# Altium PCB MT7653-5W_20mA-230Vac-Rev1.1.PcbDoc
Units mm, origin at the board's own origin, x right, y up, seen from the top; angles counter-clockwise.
Board outline 45.76 x 45.99 mm, 2 copper layers (Top Layer, Bottom Layer); 33 components, 55 nets, 78 pads, 0 vias.
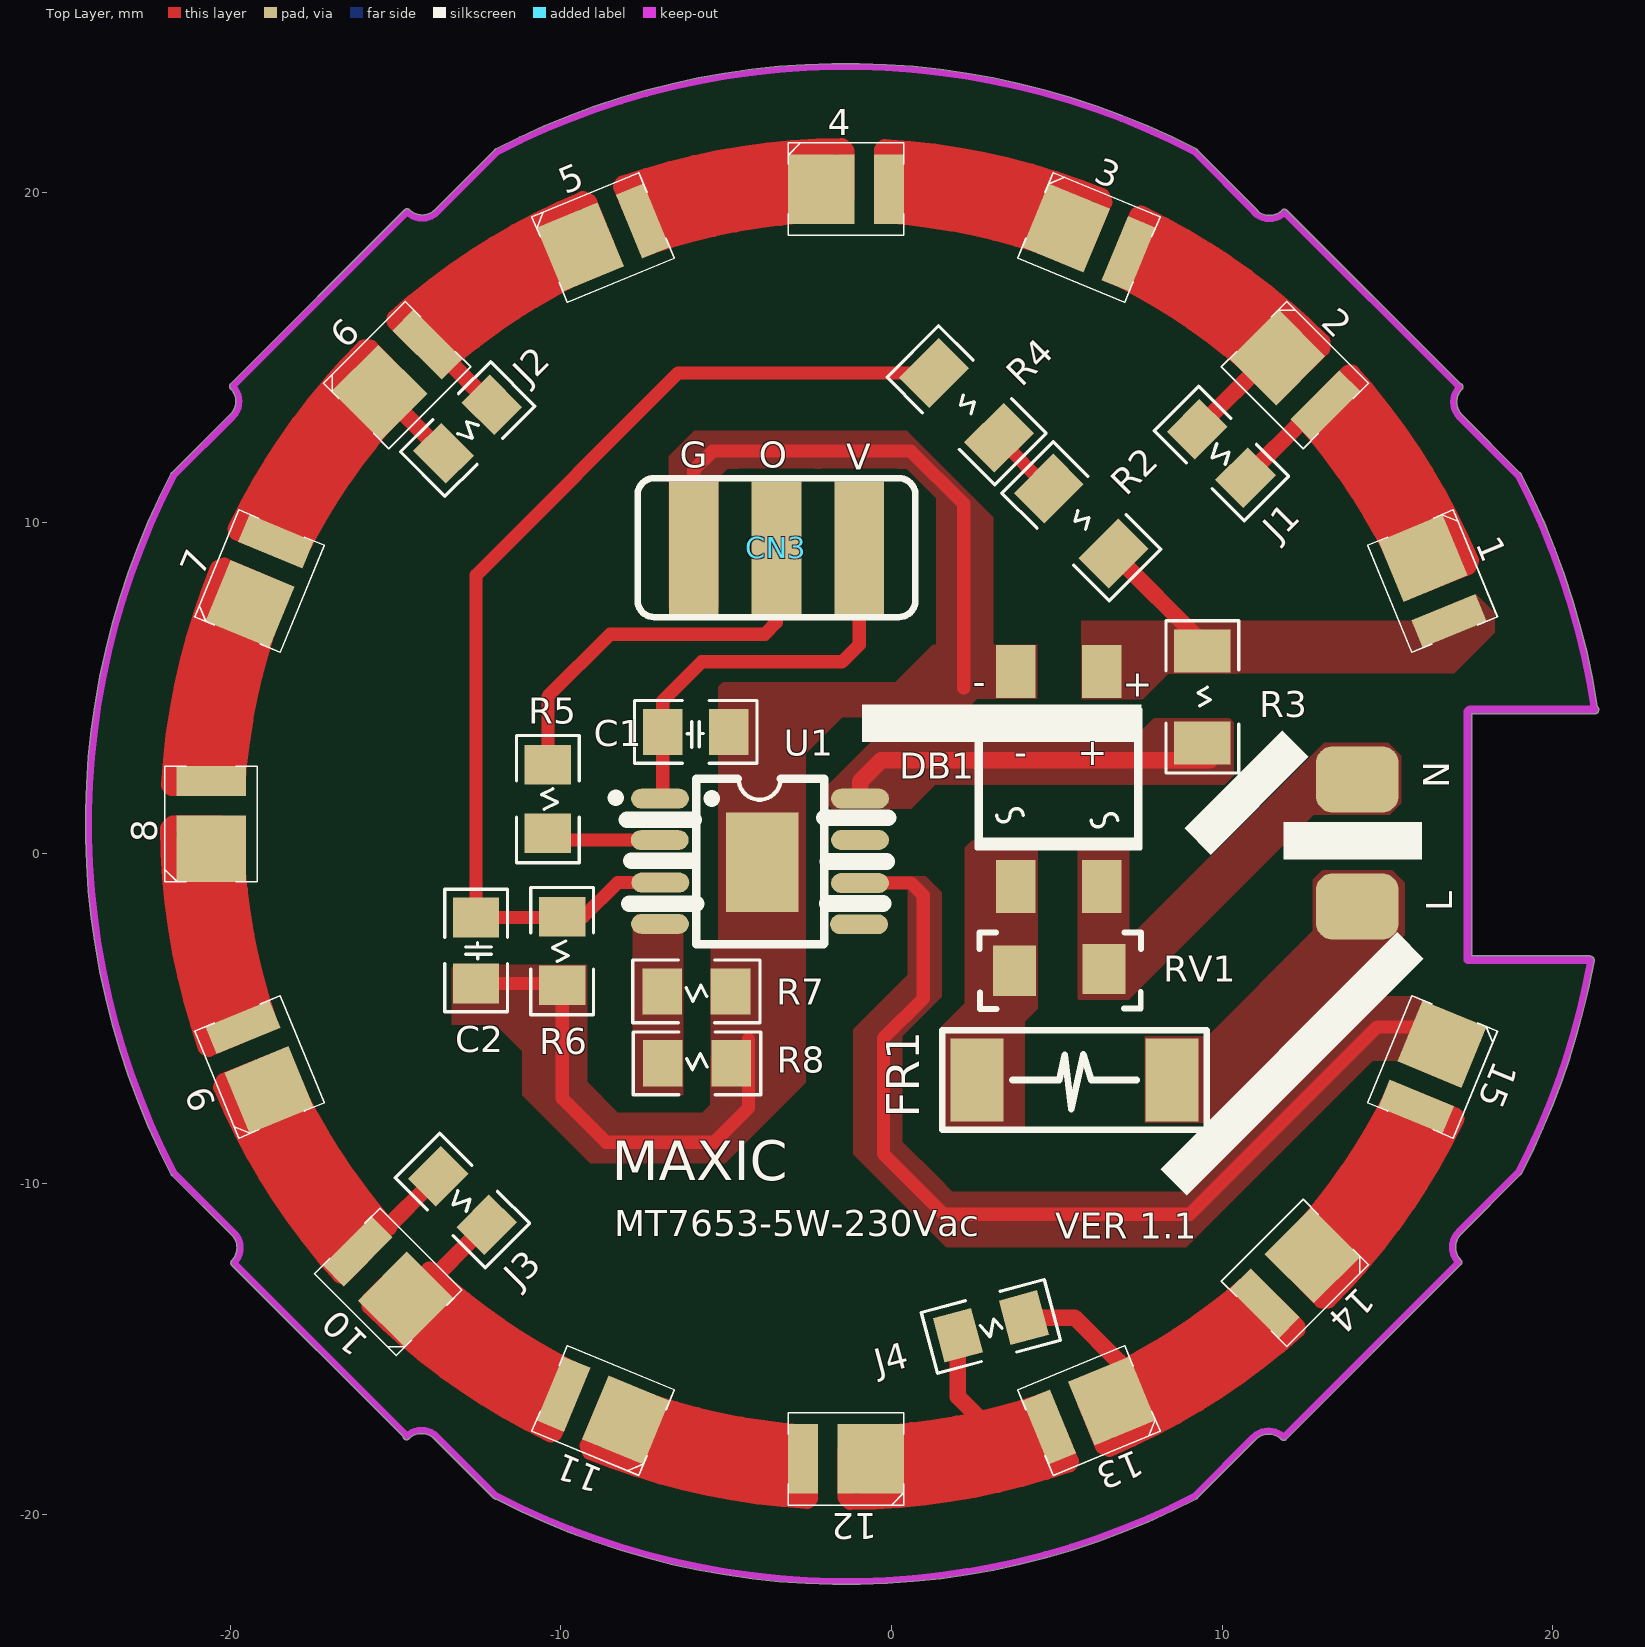
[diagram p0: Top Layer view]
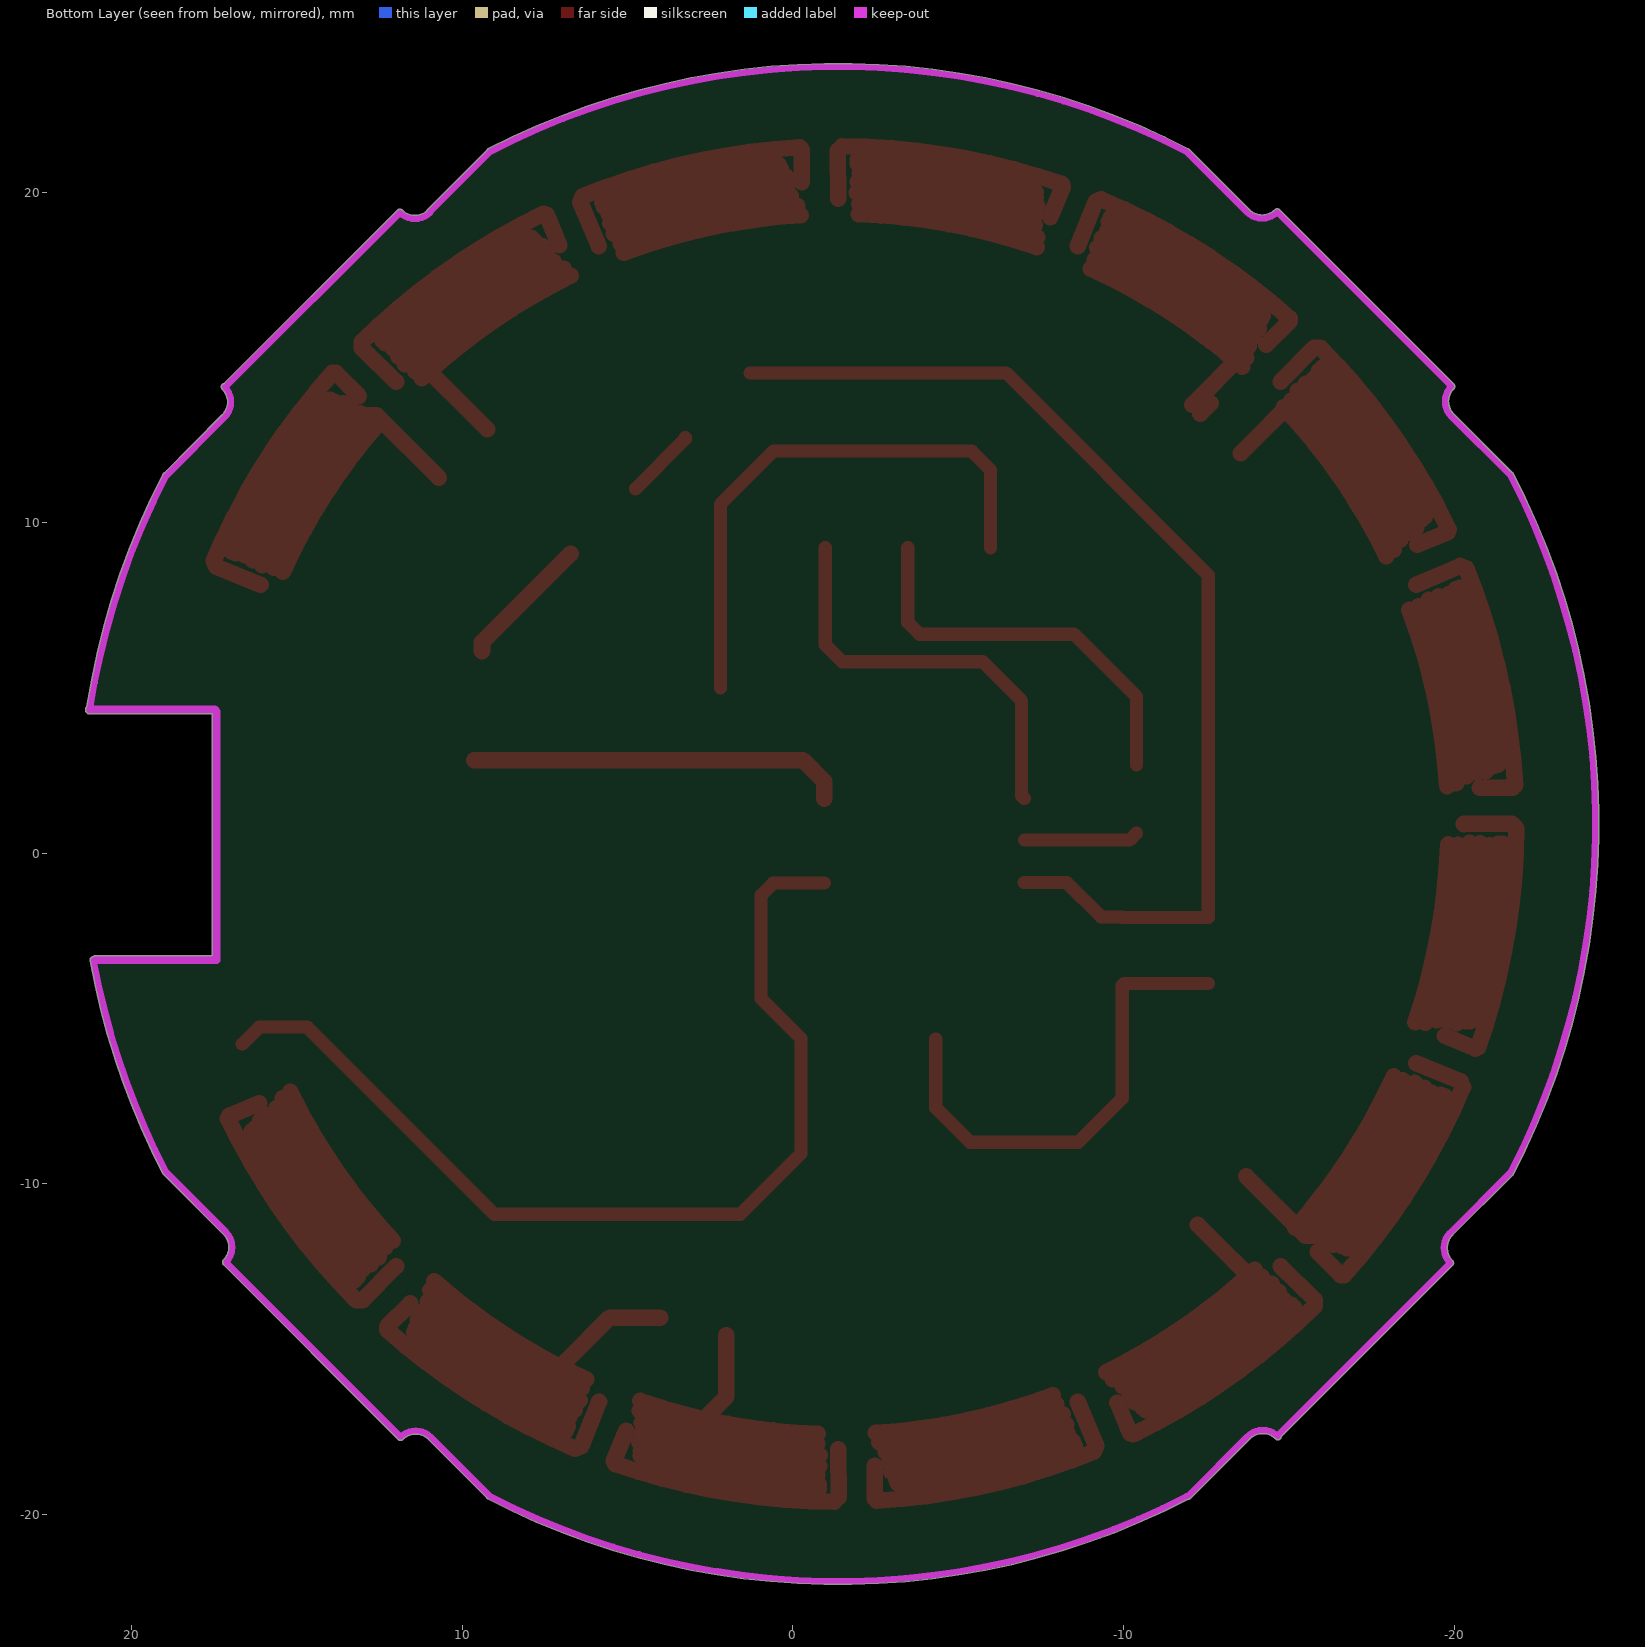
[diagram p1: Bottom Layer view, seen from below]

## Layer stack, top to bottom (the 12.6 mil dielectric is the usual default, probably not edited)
Top Solder: solder mask 0.0102, Solder Resist, Dk 3.5
Top Layer: signal copper 0.0356
Dielectric1: dielectric 0.32, FR-4, Dk 4.8
Bottom Layer: signal copper 0.0356
Bottom Solder: solder mask 0.0102, Solder Resist, Dk 3.5

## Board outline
-19.954,-12.457 cw(c-19.884,-12.385) -19.984,-12.385 cw(c-19.884,-12.385) -19.954,-12.314 ccw(c-20.34,-11.929) -19.795,-11.929 ccw(c-20.34,-11.929) -19.955,-11.543 -21.744,-9.754 cw(c-21.703,-9.662) -21.792,-9.708 cw(c-1.378,0.888) -21.792,11.483 cw(c-21.703,11.437) -21.746,11.528 -19.991,13.283 cw(c-19.92,13.212) -19.99,13.284 ccw(c-20.376,13.669) -19.831,13.669 ccw(c-20.376,13.669) -19.99,14.054 ccw(c-20.376,13.669) -19.991,14.054 -19.99,14.054 cw(c-19.92,14.125) -19.991,14.196 -14.723,19.464 -14.722,19.465 -14.723,19.464 cw(c-14.651,19.394) -14.651,19.494 cw(c-14.651,19.394) -14.58,19.464 cw(c-14.195,19.85) -14.58,19.465 -14.58,19.464 ccw(c-14.195,19.85) -13.809,19.465 -12.018,21.256 cw(c-11.927,21.213) -11.973,21.302 cw(c-1.378,0.888) 9.211,21.305 cw(c9.165,21.216) 9.258,21.255 11.051,19.462 cw(c10.98,19.391) 11.076,19.421 ccw(c11.427,19.838) 11.812,19.452 cw(c11.883,19.381) 11.883,19.482 cw(c11.883,19.381) 11.955,19.452 11.954,19.452 11.955,19.452 17.201,14.206 cw(c17.182,14.107) 17.282,14.107 cw(c17.182,14.107) 17.253,14.036 ccw(c17.638,13.651) 17.251,13.267 cw(c17.181,13.195) 17.252,13.266 19.004,11.505 cw(c18.959,11.416) 19.048,11.462 cw(c-1.378,0.888) 21.347,4.436 cw(c21.26,4.343) 21.387,4.343 cw(c21.26,4.343) 21.26,4.216 17.554,4.216 17.554,-3.098 21.091,-3.098 cw(c21.091,-3.226) 21.177,-3.131 cw(c21.149,-3.228) 21.25,-3.228 cw(c21.149,-3.228) 21.248,-3.246 cw(c-1.378,0.888) 19.051,-9.68 cw(c18.962,-9.634) 19.013,-9.721 cw(c18.936,-9.656) 19.007,-9.727 17.217,-11.526 cw(c17.146,-11.455) 17.217,-11.526 ccw(c17.602,-11.911) 17.216,-12.296 cw(c17.146,-12.368) 17.246,-12.368 cw(c17.146,-12.368) 17.217,-12.439 11.93,-17.725 cw(c11.859,-17.654) 11.788,-17.725 ccw(c11.403,-18.111) 11.018,-17.725 ccw(c11.403,-18.111) 11.017,-17.725 cw(c10.946,-17.654) 11.017,-17.725 ccw(c10.946,-17.654) 11.018,-17.725 11.017,-17.725 9.263,-19.48 cw(c9.172,-19.438) 9.218,-19.527 cw(c-1.378,0.888) -11.952,-19.538 cw(c-11.906,-19.449) -11.963,-19.531 cw(c-11.961,-19.431) -12.032,-19.502 -13.828,-17.706 cw(c-13.757,-17.635) -13.828,-17.706 ccw(c-14.214,-18.091) -14.573,-17.681 cw(c-14.651,-17.618) -14.594,-17.7 ccw(c-14.214,-18.091) -14.599,-17.706 cw(c-14.67,-17.635) -14.77,-17.641

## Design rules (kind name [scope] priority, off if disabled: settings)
Clearance [All] p1: gap=0.4
ComponentClearance [All] p1 off: gap=0.254 collisioncheckmode=3 verticalgap=0.254 showdistances=FALSE
Height [All] p1 off: minheight=0 maxheight=25.4 prefheight=12.7
HoleSize [All] p1 off: absolutevalues=TRUE maxlimit=2.54 minlimit=0.025 maxpercent=80.000 minpercent=20.000
HoleToHoleClearance [All] p1 off: gap=0.254 allowstackedmicrovias=TRUE
LayerPairs [All] p1 off: enforce=TRUE
MinimumSolderMaskSliver [All] p1 off: minsoldermaskwidth=0.254
NetAntennae [All] p1 off: netantennaetolerance=0
PolygonConnect [All] p1: connectstyle=Direct reliefconductorwidth=0.254 reliefentries=4 polygonreliefangle="90 Angle" airgapwidth=0.254
RoutingVias [All] p1: holewidth=0.711 width=1.27 viastyle="Through Hole" minholewidth=0.711 minwidth=1.27 maxholewidth=0.711 maxwidth=1.27
SilkToSilkClearance [All] p1 off: silktosilkclearance=0.254
SilkToSolderMaskClearance SilkscreenOverComponentPads [IsPad] p1 off: minsilkscreentomaskgap=0.254 clearancetoexposedcopper=TRUE
SolderMaskExpansion [All] p1: expansion=0.102
UnRoutedNet [All] p1 off:
UnpouredPolygon [All] p1 off:
Width [All] p1: maxlimit=3 minlimit=0.254 preferedwidth=0.5
19 further rules are at their usual default settings.

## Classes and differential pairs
component class MT7865-20W: Rl T1*1 T1*2

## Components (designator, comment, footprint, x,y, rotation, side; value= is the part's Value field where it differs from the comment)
1 "Comment" "LED 2835亿光/艾笛森/国星/普瑞（阻焊）新" 16.361,8.235 r292.5 top
2 "Comment" "LED 2835亿光/艾笛森/国星/普瑞（阻焊）新" 12.199,14.464 r315 top
3 "Comment" "LED 2835亿光/艾笛森/国星/普瑞（阻焊）新" 5.97,18.626 r337.5 top
4 "Comment" "LED 2835亿光/艾笛森/国星/普瑞（阻焊）新" -1.378,20.087 r0 top
5 "Comment" "LED 2835亿光/艾笛森/国星/普瑞（阻焊）新" -8.725,18.626 r22.5 top
6 "Comment" "LED 2835亿光/艾笛森/国星/普瑞（阻焊）新" -14.954,14.464 r45 top
7 "Comment" "LED 2835亿光/艾笛森/国星/普瑞（阻焊）新" -19.116,8.235 r67.5 top
8 "Comment" "LED 2835亿光/艾笛森/国星/普瑞（阻焊）新" -20.578,0.887 r90 top
9 "Comment" "LED 2835亿光/艾笛森/国星/普瑞（阻焊）新" -19.116,-6.46 r112.5 top
10 "Comment" "LED 2835亿光/艾笛森/国星/普瑞（阻焊）新" -15.223,-12.958 r135 top
11 "Comment" "LED 2835亿光/艾笛森/国星/普瑞（阻焊）新" -8.725,-16.851 r157.5 top
12 "Comment" "LED 2835亿光/艾笛森/国星/普瑞（阻焊）新" -1.378,-18.313 r180 top
13 "Comment" "LED 2835亿光/艾笛森/国星/普瑞（阻焊）新" 5.97,-16.851 r202.5 top
14 "Comment" "LED 2835亿光/艾笛森/国星/普瑞（阻焊）新" 12.199,-12.689 r225 top
15 "Comment" "LED 2835亿光/艾笛森/国星/普瑞（阻焊）新" 16.361,-6.46 r247.5 top
C1 "Comment" C/S-0805(T) -5.922,3.671 r180 top
C2 "Comment" C/S-0805(T) -12.567,-2.938 r270 top
CN3 "Comment" "SW/D 3PIN H600公端子 P2.5 贴片" -3.48,9.246 r180 top locked
DB1 "Comment" "BD-MB10G/MMB1010 (B)" 5.052,2.252 r90 top
FR1 "Comment" RXM-0207 5.537,-6.854 r0 top locked
J1 "Comment" R/S-0805(T) 9.974,12.095 r135 top
J2 "Comment" R/S-0805(T) -12.818,12.831 r225 top
J3 "Comment" R/S-0805(T) -12.98,-10.5 r135 top
J4 "Comment" R/S-0805(T) 3.005,-14.307 r195 top
R2 "Comment" R/S-1206(T) 5.735,10.047 r135 top
R3 "Comment" R/S-1206(T) 9.399,4.731 r90 top locked
R4 "Comment" R/S-1206(T) 2.268,13.55 r135 top
R5 "Comment" R/S-0805(T) -10.394,1.642 r270 top
R6 "Comment" R/S-0805(T) -9.963,-2.956 r90 top
R7 "Comment" R/S-0805(T) -5.904,-4.177 r180 top
R8 "Comment" R/S-0805(T) -5.886,-6.351 r0 top
RV1 "Comment" C/S-1206(T)阻焊 5.106,-3.549 r0 top
U1 "Comment" "U IC   SO-8EP/SOIC-8-EP   (B)" -3.982,-0.244 r0 top locked

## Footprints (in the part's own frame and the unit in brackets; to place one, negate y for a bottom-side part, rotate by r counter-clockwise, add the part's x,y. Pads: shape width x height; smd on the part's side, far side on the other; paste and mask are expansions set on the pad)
"BD-MB10G/MMB1010 (B)" [mm]
  rect 1.6x1.2 smd: 1(-3.25,-1.3) 2(3.25,-1.3) 3(-3.25,1.3) 4(3.25,1.3)
  silkscreen extent -2.1,-2.47 2.1,2.47
C/S-0805(T) [mm]
  rect 1.2x1.4 smd: 1(-1,0) 2(1,0)
  silkscreen extent -1.85,-0.95 1.85,0.95
C/S-1206(T)阻焊 [mil]
  rect 51.18x60 smd: 1(-54.63,0) 2(52,2)
  silkscreen extent -96,-46 96,46
"LED 2835亿光/艾笛森/国星/普瑞（阻焊）新" [mm]
  rect 0.9x2.1 smd: A(1.3,0.001)
  rect 2x2.1 smd: K(-0.75,0.001)
  silkscreen extent -1.75,-1.4 1.75,1.4
R/S-0805(T) [mm]
  rect 1.2x1.4 smd: 1(-1.035,0) 2(1.035,0)
  silkscreen extent -1.93,-0.95 1.93,0.95
R/S-1206(T) [mm]
  rect 1.3x1.7 smd: 1(-1.387,0) 2(1.387,0)
  silkscreen extent -2.3,-1.1 2.3,1.1
RXM-0207 [mm]
  rect 1.6x2.5 smd: 1(-2.95,0) 2(2.95,0)
  silkscreen extent -4,-1.5 4,1.5
"SW/D 3PIN H600公端子 P2.5 贴片" [mm]
  rect 1.5x4 smd: 1(-2.5,0) 2(0,0) 3(2.5,0)
  silkscreen extent -4.2,-2.1 4.2,2.1
"U IC   SO-8EP/SOIC-8-EP   (B)" [mm]
  rect 2.2x3.002 smd: 0(0.073,-0.028)
  oval 1.75x0.6 smd: 1(-3.02,1.9) 2(-3.03,0.645) 3(-3.01,-0.64) 4(-3.02,-1.89) 5(3,-1.9) 6(3.025,-0.655) 7(3.03,0.65) 8(3.03,1.9)
  silkscreen extent -4.36,-2.5 3.87,2.51

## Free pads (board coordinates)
  rrect50% 2.5x2 smd: 2(14.086,-1.609) 2(14.086,2.234)

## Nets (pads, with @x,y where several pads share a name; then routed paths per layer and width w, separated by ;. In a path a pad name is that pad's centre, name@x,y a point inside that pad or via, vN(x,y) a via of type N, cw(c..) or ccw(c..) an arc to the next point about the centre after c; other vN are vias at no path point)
1: 1.K 2.A | length 47.9
  Top Layer w0.5: 2.A@12.448,13.105 cw(c-1.378,0.887) 1.K@15.421,8.517 ; 2.A@12.717,13.231 cw(c-1.108,1.013) 1.K@15.691,8.643 ; 2.A@13.076,13.303 cw(c-0.749,1.085) 1.K@16.05,8.714 ; 2.A@13.121,13.831 13.824,14.534 13.921,14.534 cw(c-1.378,0.887) 17.515,8.846 17.439,8.667 1.K@16.098,8.126 ; 2.A@13.364,13.446 cw(c-0.462,1.229) 1.K@16.337,8.858 ; 2.A@13.597,13.608 cw(c-0.228,1.39) 1.K@16.571,9.02 ; 2.A@13.866,13.662 cw(c0.041,1.444) 1.K@16.84,9.074 ; 13.992,13.716 cw(c0.167,1.498) 1.K@16.966,9.127
2: 2.K 3.A | length 47.9
  Top Layer w0.5: 3.A@6.72,17.466 cw(c-1.378,0.887) 2.K@11.223,14.365 ; 3.A@6.921,17.685 cw(c-1.177,1.107) 2.K@11.424,14.584 ; 3.A@7.065,18.394 7.445,19.312 7.534,19.349 cw(c-1.378,0.887) 13.031,15.47 13.029,15.276 2.K@11.998,14.262 ; 3.A@7.225,17.889 cw(c-0.872,1.311) 2.K@11.728,14.788 ; 3.A@7.435,18.131 cw(c-0.662,1.553) 2.K@11.938,15.03 ; 3.A@7.589,18.37 cw(c-0.508,1.792) 2.K@12.092,15.269 ; 3.A@7.818,18.523 cw(c-0.28,1.945) 2.K@12.321,15.422 ; 7.913,18.621 cw(c-0.184,2.043) 2.K@12.416,15.52
3: 3.K 4.A | length 47.9
  Top Layer w0.5: 4.A@-0.278,20.292 -0.278,21.286 -0.209,21.354 cw(c-1.378,0.887) 6.354,19.874 6.426,19.694 3.K@5.861,18.363 ; 4.A@-0.241,19.302 cw(c-1.378,0.887) 3.K@5.106,18.161 ; 4.A@-0.139,19.582 cw(c-1.276,1.167) 3.K@5.208,18.44 ; 4.A@0.064,19.887 cw(c-1.073,1.472) 3.K@5.411,18.745 ; 4.A@0.166,20.191 cw(c-0.971,1.776) 3.K@5.512,19.05 ; 4.A@0.216,20.471 cw(c-0.92,2.056) 3.K@5.563,19.329 ; 4.A@0.369,20.699 cw(c-0.768,2.284) 3.K@5.716,19.558 ; 0.42,20.826 cw(c-0.717,2.411) 3.K@5.766,19.685
4: 4.K 5.A | length 47.9
  Top Layer w0.5: 5.A@-7.787,19.236 -8.167,20.154 -8.131,20.243 cw(c-1.378,0.887) -1.5,21.387 -1.364,21.249 4.K@-1.377,19.803 ; 5.A@-7.399,19.59 cw(c-1.402,2.142) 4.K@-2.022,20.581 ; 5.A@-7.387,18.633 cw(c-1.391,1.184) 4.K@-2.011,19.624 ; 5.A@-7.374,18.336 cw(c-1.378,0.887) 4.K@-1.998,19.327 ; -7.348,19.996 cw(c-1.351,2.548) 4.K@-1.971,20.988 ; 5.A@-7.346,19.86 cw(c-1.349,2.411) 4.K@-1.969,20.851 ; 5.A@-7.339,19.312 cw(c-1.342,1.864) 4.K@-1.962,20.304 ; 5.A@-7.316,18.992 cw(c-1.32,1.544) 4.K@-1.94,19.983
5: 5.K 6.A | length 47.9
  Top Layer w0.5: 6.A@-14.321,15.386 -15.024,16.089 -15.024,16.186 cw(c-1.378,0.887) -9.336,19.78 -9.157,19.704 5.K@-8.616,18.363 ; -14.206,16.257 cw(c-1.988,2.432) 5.K@-9.618,19.231 ; 6.A@-14.152,16.131 cw(c-1.934,2.306) 5.K@-9.564,19.105 ; 6.A@-14.098,15.862 cw(c-1.88,2.037) 5.K@-9.51,18.836 ; 6.A@-13.936,15.629 cw(c-1.719,1.803) 5.K@-9.348,18.602 ; 6.A@-13.793,15.341 cw(c-1.575,1.516) 5.K@-9.205,18.315 ; 6.A@-13.721,14.982 cw(c-1.503,1.157) 5.K@-9.133,17.955 ; 6.A@-13.595,14.713 cw(c-1.378,0.887) 5.K@-9.007,17.686
6: 6.K 7.A | length 47.9
  Top Layer w0.5: -19.111,10.178 cw(c-2.533,2.081) 6.K@-16.01,14.681 ; 7.A@-19.013,10.083 cw(c-2.435,1.985) 6.K@-15.912,14.586 ; 7.A@-18.884,9.33 -19.802,9.71 -19.839,9.799 cw(c-1.378,0.887) -15.96,15.296 -15.766,15.294 6.K@-14.752,14.263 ; 7.A@-18.86,9.854 cw(c-2.282,1.757) 6.K@-15.759,14.357 ; 7.A@-18.622,9.7 cw(c-2.043,1.603) 6.K@-15.521,14.203 ; 7.A@-18.379,9.49 cw(c-1.801,1.393) 6.K@-15.278,13.993 ; 7.A@-18.175,9.186 cw(c-1.597,1.088) 6.K@-15.074,13.688 ; 7.A@-17.956,8.985 cw(c-1.378,0.887) 6.K@-14.855,13.488
7: 7.K 8.A | length 47.9
  Top Layer w0.5: -21.316,2.685 cw(c-2.902,1.548) 7.K@-20.175,8.031 ; 8.A@-21.189,2.634 cw(c-2.775,1.497) 7.K@-20.048,7.981 ; 8.A@-20.961,2.481 cw(c-2.546,1.345) 7.K@-19.819,7.828 ; 8.A@-20.782,1.987 -21.776,1.987 -21.844,2.055 cw(c-1.378,0.887) -20.364,8.619 -20.184,8.691 7.K@-18.853,8.126 ; 8.A@-20.681,2.431 cw(c-2.267,1.294) 7.K@-19.54,7.777 ; 8.A@-20.377,2.329 cw(c-1.962,1.192) 7.K@-19.235,7.676 ; 8.A@-20.072,2.126 cw(c-1.657,0.989) 7.K@-18.93,7.473 ; 8.A@-19.792,2.024 cw(c-1.378,0.887) 7.K@-18.651,7.371
8: 8.K 9.A | length 47.9
  Top Layer w0.5: 8.K@-21.478,0.294 ccw(c-3.038,0.914) -20.486,-5.083 ; 8.K@-21.341,0.296 ccw(c-2.901,0.916) 9.A@-20.35,-5.081 ; 8.K@-21.072,0.243 ccw(c-2.632,0.863) 9.A@-20.08,-5.134 ; 8.K@-20.794,0.303 ccw(c-2.354,0.923) 9.A@-19.803,-5.074 ; 8.K@-20.473,0.325 ccw(c-2.034,0.945) 9.A@-19.482,-5.051 ; 8.K@-20.293,0.888 -21.739,0.901 -21.877,0.765 ccw(c-1.378,0.887) -20.733,-5.866 -20.644,-5.903 9.A@-19.726,-5.522 ; 8.K@-20.114,0.254 ccw(c-1.675,0.874) 9.A@-19.123,-5.123 ; 8.K@-19.817,0.267 ccw(c-1.378,0.887) 9.A@-18.826,-5.109
9: 9.K 10.A | length 47.9
  Top Layer w0.5: 9.K@-19.721,-7.353 ccw(c-2.922,0.277) -16.747,-11.941 ; 9.K@-19.595,-7.299 ccw(c-2.796,0.331) 10.A@-16.622,-11.887 ; 9.K@-19.326,-7.245 ccw(c-2.527,0.385) 10.A@-16.352,-11.833 ; 9.K@-19.092,-7.083 ccw(c-2.294,0.546) 10.A@-16.119,-11.671 ; 9.K@-18.853,-6.351 -20.194,-6.892 -20.27,-7.071 ccw(c-1.378,0.887) -16.676,-12.759 -16.579,-12.759 10.A@-15.876,-12.056 ; 9.K@-18.805,-6.94 ccw(c-2.006,0.69) 10.A@-15.831,-11.528 ; 9.K@-18.446,-6.868 ccw(c-1.647,0.762) 10.A@-15.472,-11.456 ; 9.K@-18.176,-6.742 ccw(c-1.378,0.887) -15.203,-11.33
10: 10.K 11.A | length 47.9
  Top Layer w0.5: 10.K@-15.171,-13.745 ccw(c-2.571,-0.268) -10.668,-16.846 ; 10.K@-15.076,-13.647 ccw(c-2.475,-0.17) 11.A@-10.573,-16.748 ; 10.K@-14.847,-13.494 ccw(c-2.247,-0.017) 11.A@-10.344,-16.595 ; 10.K@-14.753,-12.487 -15.784,-13.501 -15.786,-13.695 ccw(c-1.378,0.887) -10.289,-17.574 -10.2,-17.537 11.A@-9.82,-16.619 ; 10.K@-14.694,-13.256 ccw(c-2.093,0.222) 11.A@-10.191,-16.357 ; 10.K@-14.483,-13.013 ccw(c-1.883,0.464) 11.A@-9.98,-16.114 ; 10.K@-14.179,-12.809 ccw(c-1.578,0.668) 11.A@-9.676,-15.91 ; -13.978,-12.59 ccw(c-1.378,0.887) 11.A@-9.475,-15.691
11: 11.K 12.A | length 47.9
  Top Layer w0.5: 11.K@-8.617,-16.588 -9.182,-17.919 -9.109,-18.099 ccw(c-1.378,0.887) -2.546,-19.579 -2.478,-19.511 12.A@-2.478,-18.517 ; 11.K@-8.522,-17.91 ccw(c-2.038,-0.637) -3.175,-19.052 ; 11.K@-8.471,-17.783 ccw(c-1.987,-0.51) 12.A@-3.124,-18.925 ; 11.K@-8.318,-17.554 ccw(c-1.835,-0.281) 12.A@-2.971,-18.696 ; 11.K@-8.268,-17.275 ccw(c-1.784,-0.002) 12.A@-2.921,-18.417 ; 11.K@-8.166,-16.97 ccw(c-1.682,0.303) 12.A@-2.819,-18.112 ; 11.K@-7.963,-16.665 ccw(c-1.479,0.608) 12.A@-2.616,-17.807 ; 11.K@-7.861,-16.386 ccw(c-1.378,0.887) 12.A@-2.514,-17.528
12: 12.K 13.A | length 47.9
  Top Layer w0.5: 12.K@-1.378,-18.028 -1.391,-19.474 -1.255,-19.612 ccw(c-1.378,0.887) 5.376,-18.468 5.412,-18.379 13.A@5.032,-17.461 ; 12.K@-0.815,-18.209 ccw(c-1.436,0.231) 13.A@4.561,-17.217 ; 12.K@-0.793,-18.529 ccw(c-1.413,-0.089) 13.A@4.584,-17.538 ; 12.K@-0.786,-19.076 ccw(c-1.406,-0.637) 13.A@4.591,-18.085 ; 12.K@-0.784,-19.213 ccw(c-1.404,-0.773) 4.592,-18.222 ; 12.K@-0.757,-17.552 ccw(c-1.378,0.887) 13.A@4.619,-16.561 ; 12.K@-0.744,-17.849 ccw(c-1.364,0.59) 13.A@4.632,-16.858 ; 12.K@-0.733,-18.807 ccw(c-1.353,-0.367) 13.A@4.644,-17.815
13: 13.K 14.A | length 47.9
  Top Layer w0.5: 13.K@5.861,-16.588 6.402,-17.929 6.581,-18.005 ccw(c-1.378,0.887) 12.269,-14.411 12.269,-14.314 14.A@11.566,-13.612 ; 13.K@6.252,-15.911 ccw(c-1.378,0.887) 14.A@10.84,-12.938 ; 13.K@6.378,-16.181 ccw(c-1.252,0.618) 14.A@10.966,-13.207 ; 13.K@6.449,-16.54 ccw(c-1.18,0.259) 14.A@11.038,-13.566 ; 13.K@6.593,-16.827 ccw(c-1.036,-0.029) 14.A@11.181,-13.854 ; 13.K@6.755,-17.061 ccw(c-0.875,-0.262) 14.A@11.343,-14.087 ; 13.K@6.809,-17.33 ccw(c-0.821,-0.531) 14.A@11.397,-14.357 ; 13.K@6.863,-17.456 ccw(c-0.767,-0.657) 11.451,-14.482
14: 14.K 15.A | length 47.9
  Top Layer w0.5: 14.K@11.997,-12.488 13.011,-13.519 13.205,-13.521 ccw(c-1.378,0.887) 17.084,-8.024 17.047,-7.935 15.A@16.129,-7.555 ; 14.K@12.1,-11.713 ccw(c-1.378,0.887) 15.A@15.201,-7.21 ; 14.K@12.319,-11.914 ccw(c-1.158,0.687) 15.A@15.42,-7.411 ; 14.K@12.523,-12.218 ccw(c-0.954,0.382) 15.A@15.624,-7.715 ; 14.K@12.765,-12.429 ccw(c-0.712,0.172) 15.A@15.866,-7.926 ; 14.K@13.004,-12.582 ccw(c-0.473,0.018) 15.A@16.105,-8.079 ; 14.K@13.157,-12.811 ccw(c-0.32,-0.21) 15.A@16.258,-8.308 ; 14.K@13.255,-12.906 ccw(c-0.222,-0.306) 16.356,-8.403
15: 
A: 
A1: 
A2: 
A3: 
A4: 
A5: 
A6: 
A7: 
A8: 
A9: 
A10: 
A11: 
A12: 
A13: 
A14: 
A15: 
C-: 
CS: R7.2 R8.1 U1.4
CS1: 
CS2: 
DC-: 
DW-: 
GND: C1.1 C2.2 CN3.3 DB1.4 R6.1 R7.1 R8.2 U1.0 | length 31.7
  Top Layer w0.4: C2.2 -10.016,-3.938 R6.1 -9.963,-7.41 -8.634,-8.739 -5.365,-8.739 -4.323,-7.698 -4.323,-5.614 ; CN3.3 -5.98,11.597 -5.41,12.167 0.584,12.167 2.184,10.566 2.184,5.004
L: DB1.3 FR1.1 RV1.1
L+: FR1.2 pad.2@14.086,-1.609
N: DB1.1 pad.2@14.086,2.234 RV1.2
OUT: 15.K U1.6 | length 30.6
  Top Layer w0.4: U1.6 0.589,-0.899 0.957,-1.268 0.957,-4.393 -0.246,-5.596 -0.246,-9.081 1.586,-10.913 9.022,-10.913 14.679,-5.255 16.136,-5.255 15.K
OUT1: 
OUT2: 
PWM: R5.2 U1.2 | length 3.5
  Top Layer w0.4: R5.2 -10.188,0.401 U1.2
PWM+: CN3.2 R5.1 | length 13.5
  Top Layer w0.4: -10.394,3.957 R5.1 -10.394,4.745 -8.509,6.629 -3.835,6.629 -3.48,6.985 CN3.2
R2+: R2.2 R4.1 | length 2.2
  Top Layer w0.4: R4.1 3.25,12.533 R2.2
RD: C2.1 R4.2 R6.2 U1.3 | length 32.8
  Top Layer w0.4: U1.3 -8.286,-0.884 -9.323,-1.921 R6.2 -9.98,-1.938 C2.1 -12.567,8.413 -6.449,14.531 R4.2
SEL: 
VBUS: 
VCC: C1.2 CN3.1 U1.1 | length 12.6
  Top Layer w0.4: U1.1 -6.922,1.736 C1.2 -6.922,4.61 -5.74,5.791 -1.499,5.791 -0.98,6.31 CN3.1
VDC+: 
VIN: R3.1 U1.8 | length 11.4
  Top Layer w0.5: U1.8 -0.952,2.175 -0.304,2.823 R3.1@9.632,2.823
VLED+: 1.A DB1.2 R2.1 R3.2 | length 4.1
  Top Layer w0.5: R2.1 9.399,6.383 R3.2
W-: 
pads on no net: J1.1 J1.2 J2.1 J2.2 J3.1 J3.2 J4.1 J4.2 U1.5 U1.7
copper on no net: | length 27.5
  Top Layer w0.5: -16.087,-11.559 -15.503,-11.559 -13.712,-9.768 ; -15.818,13.855 -15.809,13.855 ; -15.278,13.993 -15.278,13.827 -13.55,12.099 ; -14.309,-13.373 -14.309,-13.292 -12.248,-11.231 ; -13.591,15.759 -13.591,15.067 -12.087,13.563 ; -13.088,15.938 -12.639,15.489 ; -12.639,13.612 -12.32,13.294 ; 2.005,-14.575 2.005,-16.433 3.292,-17.72 ; 4.005,-14.039 5.539,-14.039 6.866,-15.367 6.866,-16.48 ; 9.242,12.827 11.445,15.03 11.938,15.03 ; 10.705,11.363 12.587,13.244 12.955,13.244

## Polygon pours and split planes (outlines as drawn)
GND on Top Layer "Keep-Out Layer-No Net" (solid, remove dead copper, pour order 326): 3.073,5.41 3.073,10.16 2.21,11.024 0.457,12.776 -1.778,12.776 -5.969,12.776 -6.528,12.217 -6.731,12.014 -6.731,7.442 -5.232,7.442 -5.232,11.354 -4.978,11.608 -4.953,11.633 0,11.633 0.457,11.633 0.686,11.405 1.346,10.744 1.346,5.512
OUT on Top Layer "Keep-Out Layer-No Net" (solid, remove dead copper, pour order 298): -0.336,-0.693 1.029,-0.693 1.119,-0.783 1.514,-1.178 1.514,-1.394 1.514,-4.339 0.993,-4.86 0.329,-5.524 0.329,-6.387 0.329,-8.721 1.424,-9.817 1.837,-10.23 4.208,-10.23 8.914,-10.23 9.201,-9.943 14.823,-4.321 15.577,-4.321 15.9,-4.321 16.655,-5.075 15.451,-6.279 15.308,-6.279 14.553,-6.279 13.153,-7.68 8.914,-11.918 7.657,-11.918 1.658,-11.918 -0.372,-9.889 -1.162,-9.099 -1.162,-8.165 -1.162,-5.327 -0.084,-4.249 0.49,-3.675 0.49,-2.274 0.49,-1.016 0.373,-0.899 -0.957,-0.899
VLED+ on Top Layer "Keep-Out Layer-No Net" (solid, remove dead copper, pour order 300): 10.476,5.449 17.014,5.449 18.235,6.671 18.235,7.281 17.679,7.838 16.87,7.03 15.721,7.03 8.106,7.03 7.782,6.707 7.172,6.096 7.172,5.413
GND on Top Layer "Keep-Out Layer-No Net" (solid, remove dead copper, pour order 302): -3.82,-8.165 -2.599,-6.943 -2.599,-5.614 -4.467,-5.614 -4.539,-5.542 -4.898,-5.542 -5.455,-6.099 -5.49,-6.135 -5.49,-8.003
GND on Top Layer "Keep-Out Layer-No Net" (solid, remove dead copper, pour order 304): -13.106,-3.369 -9.226,-3.369 -9.208,-3.351 -9.208,-6.907 -8.364,-7.752 -8.274,-7.841 -5.724,-7.841 -5.041,-7.159 -5.041,-6.62 -4.323,-6.62 -3.82,-7.123 -3.82,-8.165 -4.09,-8.434 -5.024,-9.368 -8.005,-9.368 -9.119,-9.368 -10.106,-8.38 -11.166,-7.321 -11.166,-5.991 -11.974,-5.183 -13.303,-5.183 -13.303,-3.351 -13.285,-3.333
GND on Top Layer "Keep-Out Layer-No Net" (solid, remove dead copper, pour order 306): -5.473,-7.123 -5.473,-2.884 -3.928,-1.34 -2.599,-2.669 -2.599,-5.902 -3.82,-7.123
CS on Top Layer "Keep-Out Layer-No Net" (solid, remove dead copper, pour order 308): -7.825,-1.968 -7.825,-7.321 -6.317,-7.321 -6.299,-7.303 -6.299,-1.879 -6.317,-1.861 -7.718,-1.861
GND on Top Layer "Keep-Out Layer-No Net" (solid, remove dead copper, pour order 312): 4.334,6.311 1.245,6.311 0.58,5.647 0.113,5.18 -1.934,5.18 -5.095,5.18 -5.113,5.162 -5.239,5.036 -5.239,-2.794 -2.725,-2.794 -2.599,-2.669 -2.599,3.007 -1.485,4.12 0.131,4.12 2.035,4.12 2.592,4.677 4.388,4.677 4.406,4.695 4.406,6.311
VIN on Top Layer "Keep-Out Layer-No Net" (solid, remove dead copper, pour order 314): -1.413,1.354 0.598,1.354 1.317,2.073 10.081,2.073 10.351,2.342 10.351,4.066 10.369,4.084 7.926,4.084 7.585,3.743 7.261,3.42 4.531,3.42 -0.569,3.42 -1.593,2.396 -1.97,2.019 -1.97,1.66 -1.97,1.516 -1.809,1.354
VLED+ on Top Layer "Keep-Out Layer-No Net" (solid, remove dead copper, pour order 316): 5.735,4.659 7.603,4.659 8.106,5.162 8.375,5.431 10.279,5.431 10.458,5.431 10.476,5.413 10.476,7.03 5.735,7.03
N on Top Layer "Keep-Out Layer-No Net" (solid, remove dead copper, pour order 318): 5.663,-4.429 7.172,-4.429 8.95,-2.651 12.775,1.175 14.535,1.175 15.074,1.175 15.326,1.426 15.416,1.516 15.416,2.773 15.416,2.953 15.128,3.24 15.02,3.348 14.446,3.348 13.081,3.348 12.883,3.15 6.274,-3.459 5.663,-3.459
L+ on Top Layer "Keep-Out Layer-No Net" (solid, remove dead copper, pour order 320): 7.657,-8.147 9.848,-8.147 15.416,-2.579 15.523,-2.471 15.523,-0.998 15.523,-0.891 15.146,-0.514 13.027,-0.514 12.739,-0.801 12.739,-2.345 11.805,-3.279 9.56,-5.524 9.093,-5.524 7.657,-5.524
N on Top Layer "Keep-Out Layer-No Net" (solid, remove dead copper, pour order 322): 5.627,0.277 5.627,-4.393 5.663,-4.429 7.172,-4.429 7.19,-4.447 7.19,0.259 7.172,0.277
L on Top Layer "Keep-Out Layer-No Net" (solid, remove dead copper, pour order 324): 3.939,0.385 2.43,0.385 2.412,0.367 2.215,0.169 2.215,-3.136 2.215,-4.537 1.801,-4.95 1.46,-5.291 1.46,-8.237 1.46,-8.38 1.478,-8.398 4.029,-8.398 4.029,-5.093 4.424,-4.698 4.424,0.367 4.406,0.385

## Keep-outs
Keep-Out Layer:
  lines w0.2: -21.703,-9.662 cw(c-1.378,0.888) -21.703,11.437 ; -21.699,11.433 -19.92,13.212 ccw(c-20.376,13.669) -19.92,14.125 -14.651,19.394 ccw(c-14.195,19.85) -13.738,19.394 -11.923,21.209 ; -21.696,-9.66 -19.884,-11.472 cw(c-20.34,-11.929) -19.884,-12.385 -14.651,-17.618 ; -14.67,-17.635 cw(c-14.214,-18.091) -13.757,-17.635 -11.961,-19.431 ; -11.927,21.213 cw(c-1.378,0.888) 9.165,21.216 ; -11.906,-19.449 ccw(c-1.378,0.888) 9.172,-19.438 ; 9.168,21.203 10.98,19.391 ; 9.188,-19.413 10.946,-17.654 cw(c11.403,-18.111) 11.859,-17.654 17.146,-12.368 cw(c17.602,-11.911) 17.146,-11.455 18.936,-9.656 ; 10.97,19.381 ccw(c11.427,19.838) 11.883,19.381 17.17,14.095 ; 17.181,13.195 18.936,11.431 ; 17.182,13.194 cw(c17.638,13.651) 17.182,14.107 ; 18.959,11.416 cw(c-1.378,0.888) 21.26,4.343 ; 18.962,-9.634 ccw(c-1.378,0.888) 21.149,-3.228
  lines w0.254: 21.091,-3.226 17.427,-3.226 17.427,4.29 17.481,4.343 21.26,4.343

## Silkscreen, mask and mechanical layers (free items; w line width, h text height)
Top Overlay:
  region: 8.124,-9.548 8.923,-10.347 16.089,-3.181 15.29,-2.381
  region: 11.857,0.949 11.857,-0.181 16.048,-0.181 16.048,0.949
  region: 12.614,2.917 11.814,3.716 8.851,0.753 9.65,-0.047
  region: -0.893,4.497 -0.893,3.367 7.566,3.367 7.566,4.497
  text "O" at -3.15,12.446 h0.8 r180
  text "G" at -6.401,11.659 h0.8
  text "V" at -1.372,11.608 h0.8
  text "N" at 16.87,1.965 h0.8 r90
  text "L" at 16.96,-1.753 h0.8 r90
  text "MAXIC" at -8.458,-9.881 h1.2
  text "MT7653-5W-230Vac" at -8.382,-11.582 h0.8
  text "VER 1.1" at 4.953,-11.659 h0.8
Mechanical 1:
  lines w0.254: -11.312,-5.343 -11.312,10.657 ; -11.31,-5.345 4.69,-5.345 ; -11.183,10.708 4.69,10.708 ; 4.741,-5.345 4.741,10.706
